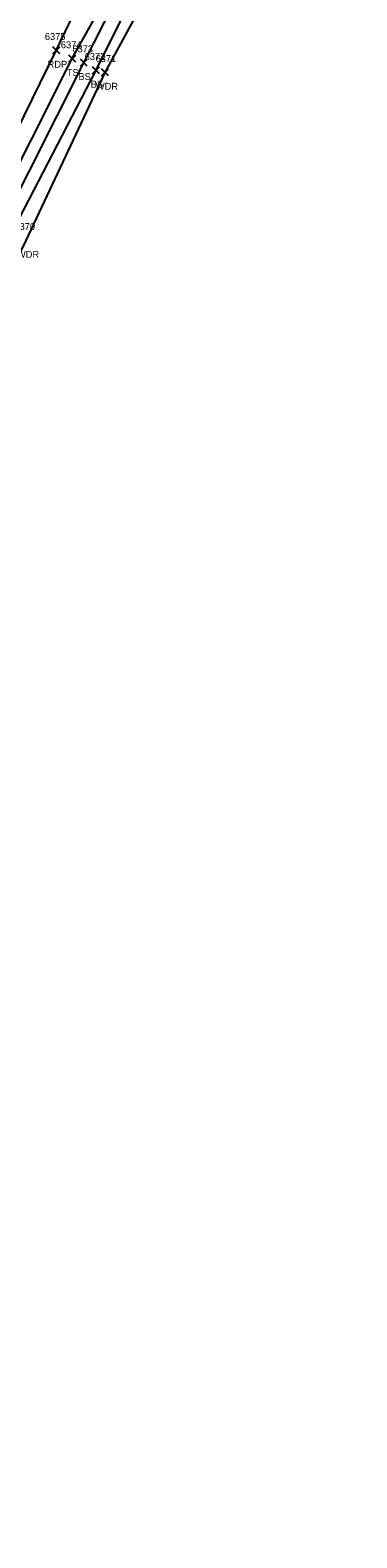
# Model space of a CAD drawing. Extents: x 1611797 to 1633212, y 298978 to 305475.
# Drawn here: x 1623332.1 to 1623426.4, y 302519.8 to 302954.8 of the extents above; entities that cross this region are included whole.
import ezdxf

# ---------------------------------------------------------------- set-up
doc = ezdxf.new("R2010")
doc.units = 0
for name, color, linetype in [('L_A', 7, 'Continuous'), ('L_I', 7, 'Continuous'), ('L_TIC', 7, 'Continuous'), ('LAWA', 7, 'Continuous'), ('LELB', 7, 'Continuous'), ('P_A', 7, 'Continuous'), ('P_I', 7, 'Continuous'), ('P_TIC', 7, 'Continuous'), ('PET', 7, 'Continuous')]:
    doc.layers.add(name, color=color, linetype=linetype)

msp = doc.modelspace()

# ---------------------------------------------------------------- linework, layer by layer
at = {"layer": 'L_TIC'}
for points in [[(1623343.26, 302945.55), (1623345.26, 302947.55)], [(1623345.26, 302945.55), (1623343.26, 302947.55)], [(1623346.59, 302944.38), (1623348.59, 302946.38)], [(1623348.59, 302944.38), (1623346.59, 302946.38)], [(1623350.13, 302942.19), (1623352.13, 302944.19)], [(1623352.13, 302942.19), (1623350.13, 302944.19)], [(1623352.71, 302941.58), (1623354.71, 302943.58)], [(1623354.71, 302941.58), (1623352.71, 302943.58)]]:
    msp.add_lwpolyline(points, dxfattribs=at)
at = {"layer": 'LAWA'}
msp.add_lwpolyline([(1623220.84, 302680.55), (1623240.35, 302713.34), (1623259.59, 302745.03), (1623275.8, 302783.76), (1623285.52, 302809.42), (1623309.65, 302850.52), (1623330.94, 302894.09), (1623353.71, 302942.58), (1623377.05, 302985.36), (1623397.1, 303029.07), (1623413.32, 303066.26), (1623426.35, 303085.97)], dxfattribs=at)
at = {"layer": 'LELB'}
for points in [[(1623217.32, 302688.18), (1623230.4, 302715.58), (1623245.63, 302751.73), (1623264.01, 302786.49), (1623270.92, 302795.82), (1623277.78, 302818.71), (1623297.88, 302857.93), (1623320.78, 302900.03), (1623344.26, 302946.55), (1623366.78, 302987.1), (1623388.58, 303034.28), (1623404.68, 303068.7), (1623410.32, 303083.51), (1623416.82, 303092.71)], [(1623220.84, 302680.55), (1623236.45, 302716.75), (1623251.98, 302748.34), (1623271.58, 302784.22), (1623284.18, 302815.43), (1623302.25, 302855.05), (1623324.11, 302898.68), (1623347.59, 302945.38), (1623368.51, 302986.67), (1623391.28, 303032.97), (1623406.76, 303068), (1623418.99, 303091.46)], [(1623285.52, 302809.42), (1623306.23, 302852.67), (1623327.56, 302897.78), (1623351.13, 302943.19), (1623371.96, 302985.14), (1623394.5, 303031.05), (1623410.54, 303067.13), (1623420.78, 303090.27), (1623418.99, 303091.46)]]:
    msp.add_lwpolyline(points, dxfattribs=at)
at = {"layer": 'P_TIC'}
for points in [[(1623338.64, 302947.93), (1623340.64, 302949.93)], [(1623340.64, 302947.93), (1623338.64, 302949.93)]]:
    msp.add_lwpolyline(points, dxfattribs=at)
at = {"layer": 'PET'}
msp.add_lwpolyline([(1623120.03, 302492.78), (1623133.04, 302521.46), (1623136.48, 302529.45), (1623140.9, 302540.16), (1623148.08, 302555.78), (1623164.16, 302589.32), (1623182.09, 302626.91), (1623191.33, 302646.49), (1623194.97, 302654.45), (1623201.31, 302667.61), (1623213.02, 302692.54), (1623225.2, 302718.17), (1623242.57, 302754.17), (1623259.21, 302788.55), (1623275.23, 302819.9), (1623295.03, 302859.4), (1623316.4, 302901.79), (1623339.64, 302948.93), (1623359.43, 302990.05)], dxfattribs=at)

# ---------------------------------------------------------------- texts
at = {"layer": 'L_A'}
for s, p in [('TS', (1623342.67, 302941.55)), ('BS', (1623346.03, 302940.38)), ('BS', (1623349.57, 302938.19)), ('WDR', (1623351.07, 302937.58)), ('WDR', (1623328.3, 302889.09))]:
    msp.add_text(s, height=2, dxfattribs=at).set_placement(p)
at = {"layer": 'L_I'}
for s, p in [('6374', (1623340.96, 302949.55)), ('6373', (1623344.28, 302948.38)), ('6372', (1623347.82, 302946.19)), ('6371', (1623350.97, 302945.58)), ('6370', (1623327.55, 302897.09))]:
    msp.add_text(s, height=2, dxfattribs=at).set_placement(p)
at = {"layer": 'P_A'}
msp.add_text('RDP', height=2, dxfattribs=at).set_placement((1623337.13, 302943.93))
at = {"layer": 'P_I'}
msp.add_text('6375', height=2, dxfattribs=at).set_placement((1623336.34, 302951.93))

doc.saveas('drawing.dxf')
